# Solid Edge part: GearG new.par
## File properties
Author: vinurabandara
Template: iso metric part.par
Last saved by: Nimesh.N
Revision: 26
Application: Solid Edge
Username: Nimesh.N
Density: 7250.000 kg/m^3
Accuracy: 0.990
Material: Iron:0.6025 , EN-GJL-250
Face Style: Gray
Fill Style: ANSI31(Iron)
Grouping: Iron\Gray Cast Iron
LibraryName: Materials-DIN
Coef. of Thermal Exp: 1.05e-05
Thermal Conductivity: 58.0
Specific Heat: 460.0
Modulus of Elasticity: 120000003072.0
Poisson's Ratio: 0.26
Yield Stress: 165593984.0
Ultimate Stress: 250000000.0
Elongation: 0.0
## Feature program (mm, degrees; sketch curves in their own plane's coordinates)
sketch for "unnamed Protrusion 1" plane through (0, 0, 0) normal (0, 0, 1) x-axis (1, 0, 0)
  circle centre (0, 0) radius 220
extrude "unnamed Protrusion 1" add finite 130 along -normal
sketch used by "unnamed Cutout 1" plane through (0, 0, 0) normal (0, 0, 1) x-axis (1, 0, 0)
  line (0, 0) -> (-16.4406, 219.3848)
  line (0, 0) -> (-13.7044, 219.5727)
  line (0, 0) -> (-38.2026, 216.6577)
  line (-3.693, 197.4655) -> (3.693, 197.4655)
  arc centre (-62.2261, 184.279) radius 60 from (-13.7044, 219.5727) to (-3.693, 197.4655) cw
  arc centre (62.2261, 184.279) radius 60 from (13.7044, 219.5727) to (3.693, 197.4655) ccw
extrude "unnamed Cutout 1" cut through along -normal
pattern "unnamed Pattern 1" of "unnamed Cutout 1"
pattern "unnamed Pattern 2"
sketch for "unnamed Cutout 2" plane through (0, 0, 0) normal (0, 0, 1) x-axis (0.365341, 0.930874, 0)
extrude "unnamed Cutout 2" cut through along -normal
sketch for "unnamed Cutout 3" plane through (0, 0, 0) normal (0, 0, 1) x-axis (0.365341, 0.930874, 0)
  line (-8.125, 39.8042) -> (-8.125, 31.468)
  line (8.125, 39.8042) -> (8.125, 31.468)
extrude "unnamed Cutout 3" cut through along -normal
pattern "unnamed Pattern 3" of "unnamed Cutout 3"
pattern "unnamed Pattern 4"
sketch used by "unnamed Protrusion 2" plane through (0, 0, 0) normal (0, 0, 1) x-axis (1, 0, 0)
  circle centre (0, 0) radius 220
extrude "unnamed Protrusion 2" add finite
sketch for "unnamed Protrusion 3" #1 plane through (0, 0, 0) normal (0, 0, 1) x-axis (0.365341, 0.930874, 0)
sketch for "unnamed Protrusion 3" #2 plane through (0, 0, 0) normal (0, 0, 1) x-axis (0.365341, 0.930874, 0)
extrude "unnamed Protrusion 3" add finite
sketch for "unnamed Protrusion 4" plane through (0, 0, 0) normal (0, 0, 1) x-axis (0.365341, 0.930874, 0)
extrude "unnamed Protrusion 4" add finite
sketch for "unnamed Protrusion 5" plane through (0, 0, 0) normal (0, 0, 1) x-axis (0.365341, 0.930874, 0)
  circle centre (0, 0) radius 150.1838
extrude "unnamed Protrusion 5" add finite
sketch for "unnamed Protrusion 6" plane through (0, 0, 0) normal (0, 0, 1) x-axis (0.365341, 0.930874, 0)
  circle centre (0, 0) radius 135.167
extrude "unnamed Protrusion 6" add finite
sketch for "unnamed Cutout 4" #1 plane through (0, 0, 0) normal (0, 0, 1) x-axis (0.365341, 0.930874, 0)
  circle centre (0, 0) radius 79
sketch for "unnamed Cutout 4" #2 plane through (0, 0, 0) normal (0, 0, 1) x-axis (0.365341, 0.930874, 0)
  circle centre (0, 0) radius 177.75
extrude "unnamed Cutout 4" cut finite 35 along -normal
mirror "unnamed Mirror 1" of "unnamed Cutout 4"
pattern "unnamed Pattern 5"
sketch for "unnamed Cutout 5" plane through (0, 0, -35) normal (0, 0, 1) x-axis (1, 0, 0)
extrude "unnamed Cutout 5" cut through along -normal
pattern "unnamed Pattern 6" of "unnamed Cutout 5"
pattern "unnamed Pattern 7"
fillet "unnamed Round 1"
fillet "Round_3" radius 10
sketch for "ExtrudedProtrusion_9" #1 plane through (0, 0, -130) normal (0, 0, -1) x-axis (-1, 0, 0)
sketch for "ExtrudedProtrusion_9" #2 plane through (0, 0, -130) normal (0, 0, -1) x-axis (-1, 0, 0)
extrude "ExtrudedProtrusion_9" add finite 15 along +normal
sketch for "ExtrudedProtrusion_10" #1 plane through (0, 0, -145) normal (0, 0, -1) x-axis (-1, 0, 0)
sketch for "ExtrudedProtrusion_10" #2 plane through (0, 0, -145) normal (0, 0, -1) x-axis (-1, 0, 0)
extrude "ExtrudedProtrusion_10" add finite 5 along -normal
Other named dimensions: "ExtrudedSurface_3": FiniteDepth = 130 mm
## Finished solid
Body 1: sheet body, 1 face, 2 edges, 0 vertices.
  Faces by surface: cylinder 1
  Edges by curve: circle 2
Body 2: solid body, 244 faces, 706 edges, 464 vertices.
  Faces by surface: cylinder 171, plane 73
  Edges by curve: line 364, circle 342
Bounding box of the edges (mm): 440.000 x 439.146 x 145.000, from (-220, -219.5727, -145) to (220, 219.5727, 0).
Cylindrical faces by radius (mm): R10 x16, R32.5 x8, R40.625 x8, R60 x84, R79 x2, R94.8 x4, R104 x1, R163.925 x4, R177.75 x2, R210 x1, R220 x42
Planar faces by outward normal: +y 1, +z 4, -y 1, -z 3, oblique 64
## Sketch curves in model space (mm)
line (0, 0, 0) -> (-38.2026, 216.6577, 0)
line (0, 0, 0) -> (-16.4406, 219.3848, 0)
line (0, 0, 0) -> (4.1138, 219.9615, 0)
line (0, 0, 0) -> (-4.1138, 219.9615, 0)
arc centre (62.2261, 184.279, 0) radius 60 from (13.7044, 219.5727, 0) through (7.5693, 209.0306, 0) to (3.693, 197.4655, 0)
line (-3.693, 197.4655, 0) -> (3.693, 197.4655, 0)
arc centre (-62.2261, 184.279, 0) radius 60 from (-13.7044, 219.5727, 0) through (-7.5693, 209.0306, 0) to (-3.693, 197.4655, 0)
line (0, 0, 0) -> (-13.7044, 219.5727, 0)
circle centre (0, 0, 0) radius 220
circle centre (0, 0, 0) radius 210
circle centre (0, 0, 0) radius 197.5
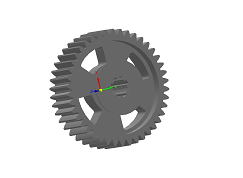
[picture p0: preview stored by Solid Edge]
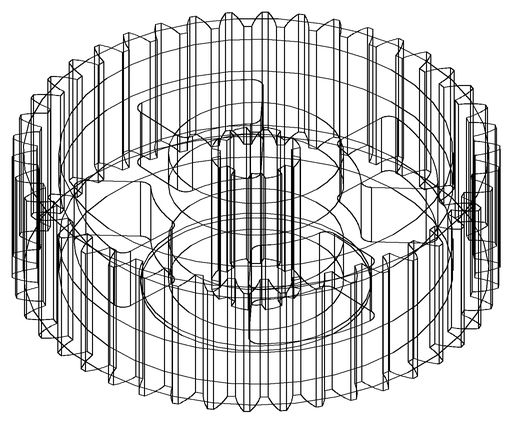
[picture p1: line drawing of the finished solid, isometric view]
